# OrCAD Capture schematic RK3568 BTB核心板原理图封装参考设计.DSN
size A3; title: 野火_EBF RK3568 底板; rev: V1.0; note: BTB连接器; note: https://yehuosm.tmall.com
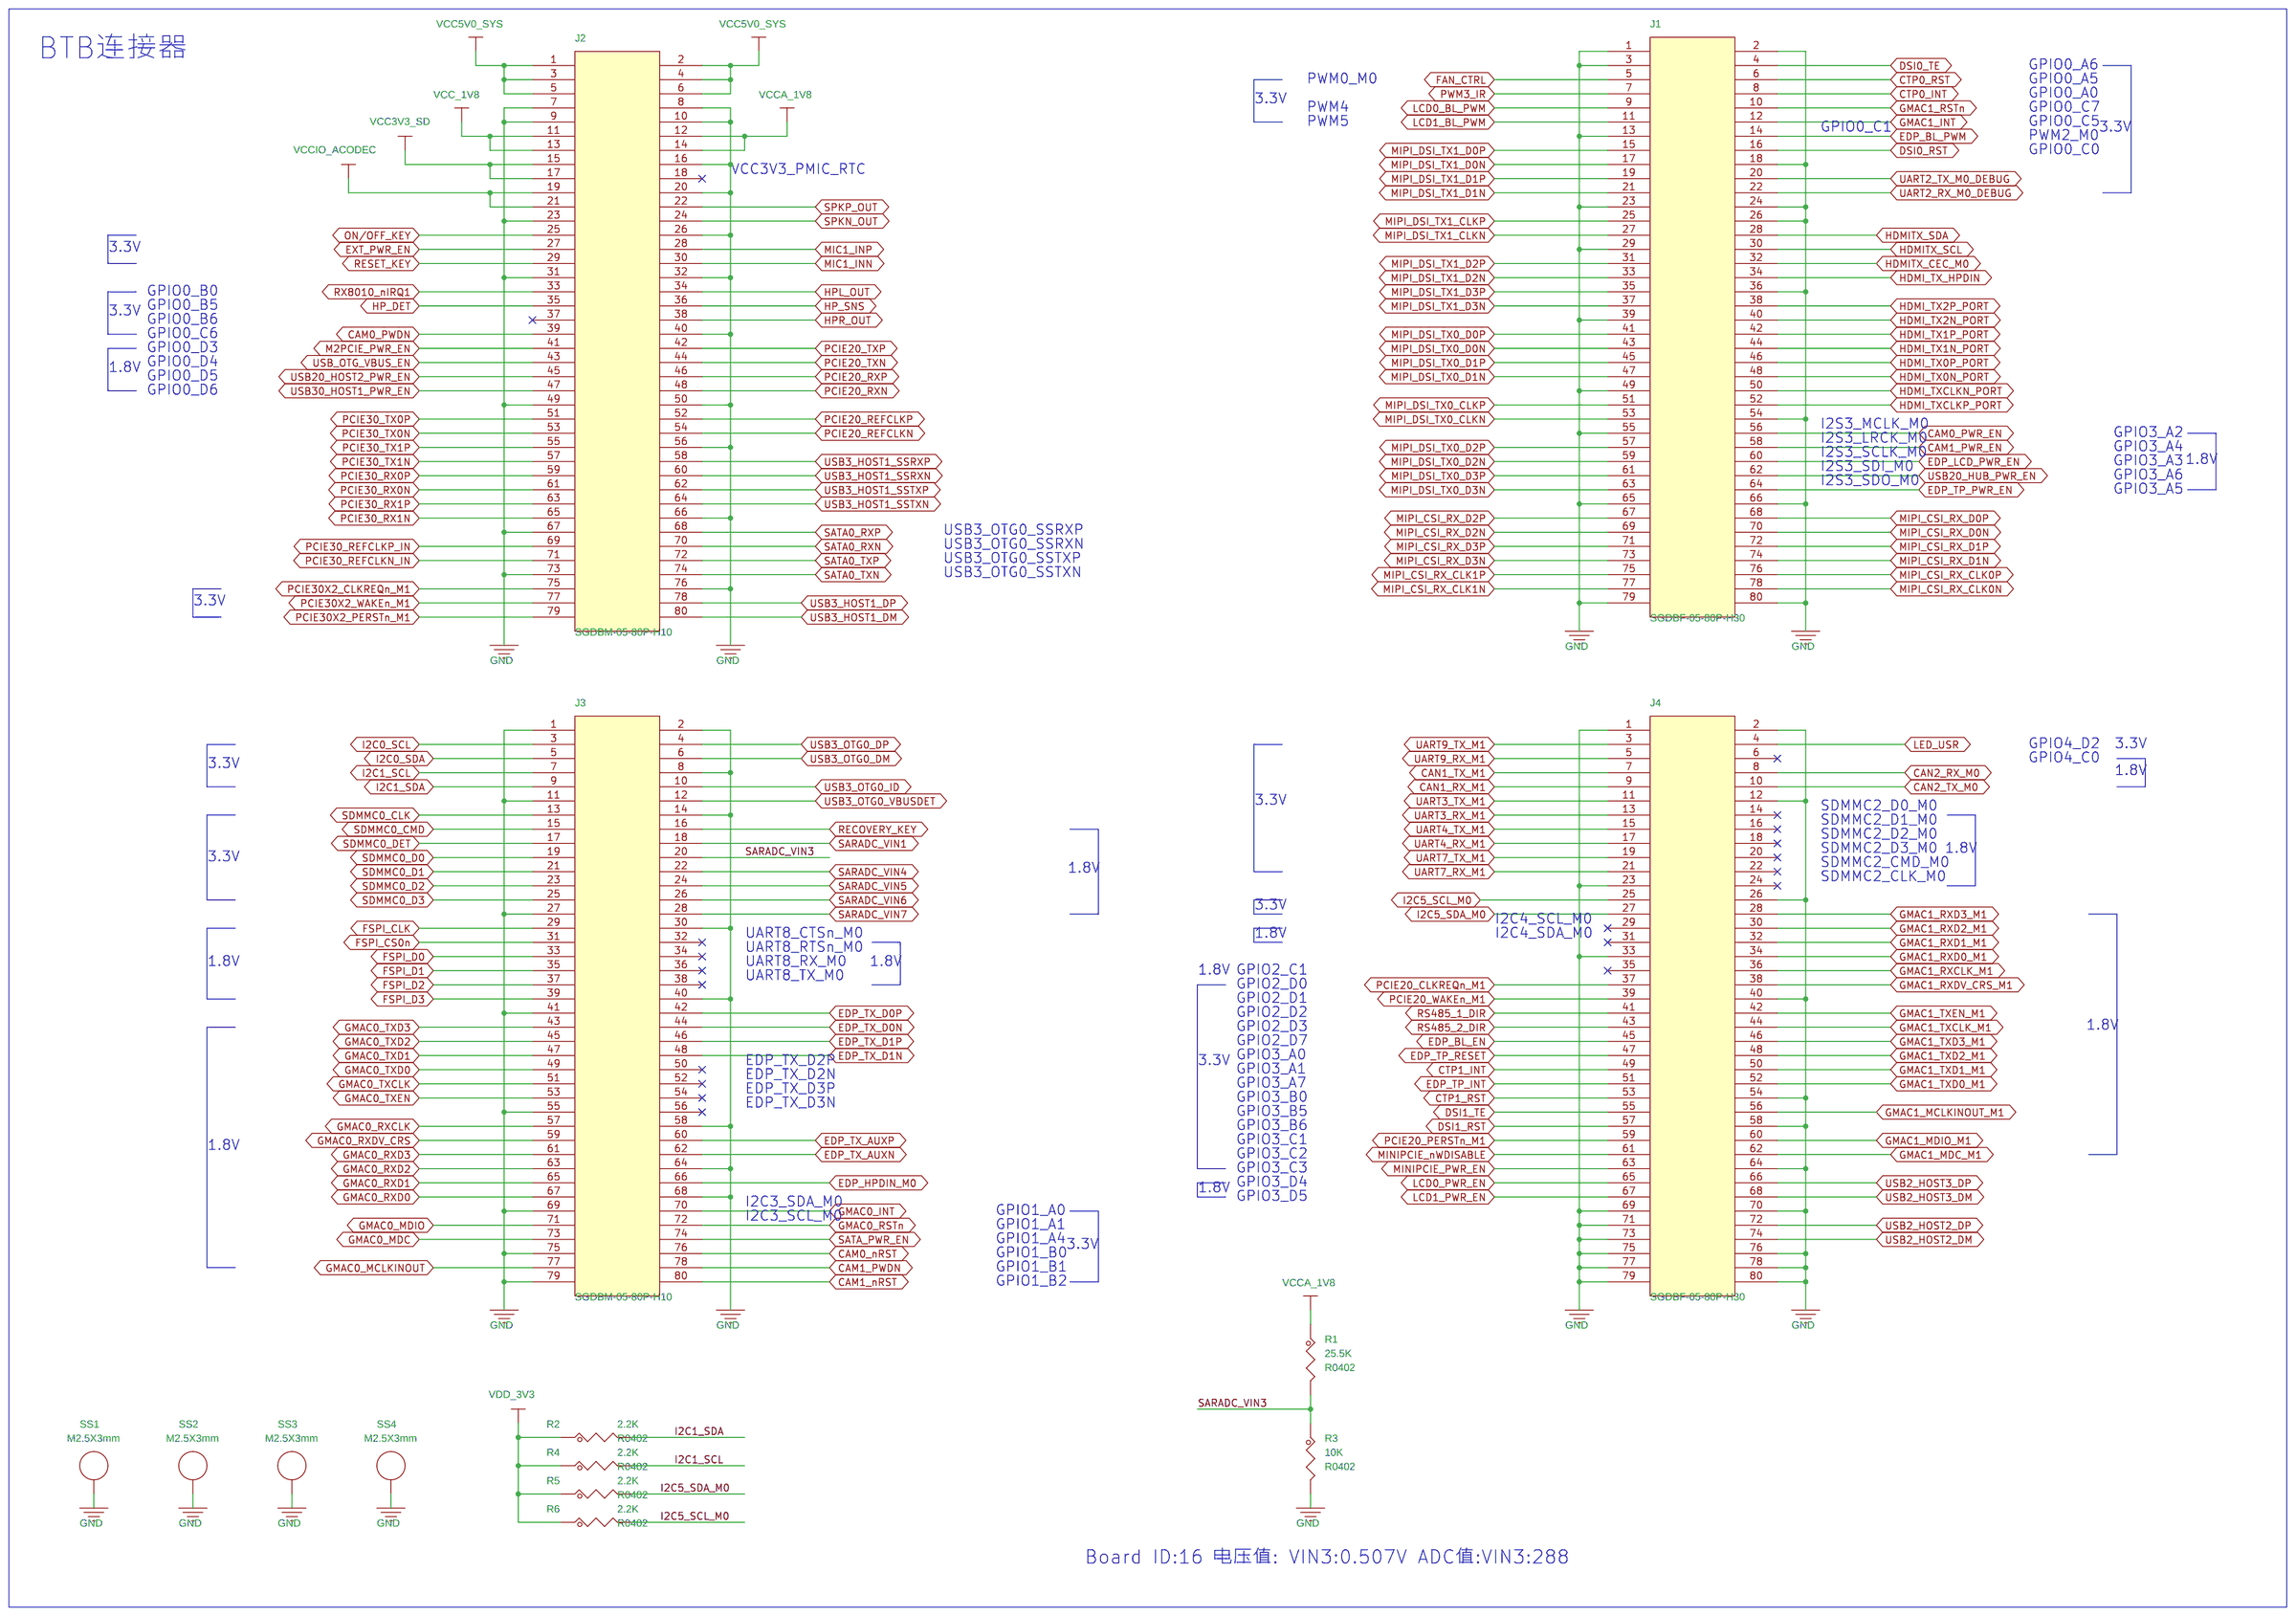
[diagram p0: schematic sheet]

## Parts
J1  SGDBF-05-80P-H30  [SGDBF-05-80P-H30]
J2  SGDBM-05-80P-H10  [SGDBM-05-80P-H10]
J3  SGDBM-05-80P-H10  [SGDBM-05-80P-H10]
J4  SGDBF-05-80P-H30  [SGDBF-05-80P-H30]
R1  25.5K  [R0402]
R2  2.2K  [R0402]
R3  10K  [R0402]
R4  2.2K  [R0402]
R5  2.2K  [R0402]
R6  2.2K  [R0402]
SS1  M2.5X3mm  [SMTSO-M2r5]
SS2  M2.5X3mm  [SMTSO-M2r5]
SS3  M2.5X3mm  [SMTSO-M2r5]
SS4  M2.5X3mm  [SMTSO-M2r5]

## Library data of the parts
J1 J4 = SGDBM-05-80P-H10: 规格: 0.5mm BTB母座2*40P 双槽 立贴式 合高4.0mm; 规格书: 山谷道_双槽板对板公母立贴式0_5mm.pdf; 类别: BTB连接器; 品牌: 山谷道; 生命周期: 量产; 条码: EBFCIS221220165510
J2 J3 = SGDBM-05-80P-H10: 规格: 0.5mm BTB公座2*40P 双槽 立贴式 合高4.0mm; 规格书: 山谷道_双槽板对板公母立贴式0_5mm.pdf; 类别: BTB连接器; 品牌: 山谷道; 生命周期: 量产; 条码: EBFCIS221220164941
R1 = RES: 规格: 贴片电阻25.5K 1% 1/16W 0402; 规格编号: CQ02WGF2552TCE; 规格书: 厚声-无铅厚膜电阻.pdf; 价格: 0.006152; 类别: 贴片电阻0402; 品牌: 厚声; 生命周期: 量产; 条码: EBF29070291
R2 R4-R6 = RES: 规格: 贴片电阻2.2K 1% 1/16W 0402; 规格编号: RI0402L2201FT; 规格书: 合科泰-RI系列电阻.pdf; 类别: 贴片电阻0402; 品牌: 合科泰; 生命周期: 量产; 条码: EBF29070051
R3 = RES: 规格: 贴片电阻10K 1% 1/16W 0402; 规格编号: 0402WGF1002TCE; 规格书: 厚声-无铅厚膜电阻.pdf; 价格: 0.002773; 类别: 贴片电阻0402; 品牌: 厚声; 生命周期: 量产; 条码: EBF29070046
SS1-SS4 = SPACER: 规格: SMT贴片螺母M2.5 台阶高度1.4MM 台阶外径：4.09MM 螺柱长度：3MM; 规格编号: SMTSO2530CTJ; 规格书: 雄和远景_SMTSO2530CTJ.pdf; 类别: 贴片螺母; 品牌: 雄和远景; 生命周期: 量产; 条码: EBFCIS221028102827

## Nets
GND: J1.1 J1.2 J1.3 J1.13 J1.18 J1.23 J1.24 J1.26 J1.29 J1.36 J1.39 J1.49 J1.54 J1.55 J1.65 J1.66 J1.79 J1.80 J2.7 J2.8 J2.9 J2.10 J2.16 J2.20 J2.23 J2.26 J2.31 J2.32 J2.40 J2.49 J2.50 J2.56 J2.66 J2.67 J2.73 J2.76 J3.1 J3.2 J3.8 J3.11 J3.14 J3.27 J3.30 J3.40 J3.41 J3.55 J3.58 J3.64 J3.68 J3.69 J3.75 J3.79 J4.1 J4.2 J4.12 J4.23 J4.26 J4.33 J4.40 J4.54 J4.58 J4.64 J4.69 J4.70 J4.71 J4.73 J4.75 J4.76 J4.77 J4.78 J4.79 J4.80 R3.2 SS1.1(NC) SS2.1(NC) SS3.1(NC) SS4.1(NC)
VCC3V3_SD: J2.15 J2.17
VCC5V0_SYS: J2.1 J2.2 J2.3 J2.4 J2.5 J2.6
VCC_1V8: J2.11 J2.13
VCCA_1V8: J2.12 J2.14 R1.1
VCCIO_ACODEC: J2.19 J2.21
VDD_3V3: R2.1 R4.1 R5.1 R6.1
CAM0_nRST: J3.76
CAM0_PWDN: J2.39
CAM0_PWR_EN: J1.56
CAM1_nRST: J3.80
CAM1_PWDN: J3.78
CAM1_PWR_EN: J1.58
CAN1_RX_M1: J4.9
CAN1_TX_M1: J4.7
CAN2_RX_M0: J4.8
CAN2_TX_M0: J4.10
CTP0_INT: J1.8
CTP0_RST: J1.6
CTP1_INT: J4.49
CTP1_RST: J4.53
DSI0_RST: J1.16
DSI0_TE: J1.4
DSI1_RST: J4.57
DSI1_TE: J4.55
EDP_BL_EN: J4.45
EDP_BL_PWM: J1.14
EDP_HPDIN_M0: J3.66
EDP_LCD_PWR_EN: J1.60
EDP_TP_INT: J4.51
EDP_TP_PWR_EN: J1.64
EDP_TP_RESET: J4.47
EDP_TX_AUXN: J3.62
EDP_TX_AUXP: J3.60
EDP_TX_D0N: J3.44
EDP_TX_D0P: J3.42
EDP_TX_D1N: J3.48
EDP_TX_D1P: J3.46
EXT_PWR_EN: J2.27
FAN_CTRL: J1.5
FSPI_CLK: J3.29
FSPI_CS0n: J3.31
FSPI_D0: J3.33
FSPI_D1: J3.35
FSPI_D2: J3.37
FSPI_D3: J3.39
GMAC0_INT: J3.70
GMAC0_MCLKINOUT: J3.77
GMAC0_MDC: J3.73
GMAC0_MDIO: J3.71
GMAC0_RSTn: J3.72
GMAC0_RXCLK: J3.57
GMAC0_RXD0: J3.67
GMAC0_RXD1: J3.65
GMAC0_RXD2: J3.63
GMAC0_RXD3: J3.61
GMAC0_RXDV_CRS: J3.59
GMAC0_TXCLK: J3.51
GMAC0_TXD0: J3.49
GMAC0_TXD1: J3.47
GMAC0_TXD2: J3.45
GMAC0_TXD3: J3.43
GMAC0_TXEN: J3.53
GMAC1_INT: J1.12
GMAC1_MCLKINOUT_M1: J4.56
GMAC1_MDC_M1: J4.62
GMAC1_MDIO_M1: J4.60
GMAC1_RSTn: J1.10
GMAC1_RXCLK_M1: J4.36
GMAC1_RXD0_M1: J4.34
GMAC1_RXD1_M1: J4.32
GMAC1_RXD2_M1: J4.30
GMAC1_RXD3_M1: J4.28
GMAC1_RXDV_CRS_M1: J4.38
GMAC1_TXCLK_M1: J4.44
GMAC1_TXD0_M1: J4.52
GMAC1_TXD1_M1: J4.50
GMAC1_TXD2_M1: J4.48
GMAC1_TXD3_M1: J4.46
GMAC1_TXEN_M1: J4.42
HDMI_TX0N_PORT: J1.48
HDMI_TX0P_PORT: J1.46
HDMI_TX1N_PORT: J1.44
HDMI_TX1P_PORT: J1.42
HDMI_TX2N_PORT: J1.40
HDMI_TX2P_PORT: J1.38
HDMI_TX_HPDIN: J1.34
HDMI_TXCLKN_PORT: J1.50
HDMI_TXCLKP_PORT: J1.52
HDMITX_CEC_M0: J1.32
HDMITX_SCL: J1.30
HDMITX_SDA: J1.28
HP_DET: J2.35
HP_SNS: J2.36
HPL_OUT: J2.34
HPR_OUT: J2.38
I2C0_SCL: J3.3
I2C0_SDA: J3.5
I2C1_SCL: J3.7 R4.2
I2C1_SDA: J3.9 R2.2
I2C5_SCL_M0: J4.25 R6.2
I2C5_SDA_M0: J4.27 R5.2
LCD0_BL_PWM: J1.9
LCD0_PWR_EN: J4.65
LCD1_BL_PWM: J1.11
LCD1_PWR_EN: J4.67
LED_USR: J4.4
M2PCIE_PWR_EN: J2.41
MIC1_INN: J2.30
MIC1_INP: J2.28
MINIPCIE_nWDISABLE: J4.61
MINIPCIE_PWR_EN: J4.63
MIPI_CSI_RX_CLK0N: J1.78
MIPI_CSI_RX_CLK0P: J1.76
MIPI_CSI_RX_CLK1N: J1.77
MIPI_CSI_RX_CLK1P: J1.75
MIPI_CSI_RX_D0N: J1.70
MIPI_CSI_RX_D0P: J1.68
MIPI_CSI_RX_D1N: J1.74
MIPI_CSI_RX_D1P: J1.72
MIPI_CSI_RX_D2N: J1.69
MIPI_CSI_RX_D2P: J1.67
MIPI_CSI_RX_D3N: J1.73
MIPI_CSI_RX_D3P: J1.71
MIPI_DSI_TX0_CLKN: J1.53
MIPI_DSI_TX0_CLKP: J1.51
MIPI_DSI_TX0_D0N: J1.43
MIPI_DSI_TX0_D0P: J1.41
MIPI_DSI_TX0_D1N: J1.47
MIPI_DSI_TX0_D1P: J1.45
MIPI_DSI_TX0_D2N: J1.59
MIPI_DSI_TX0_D2P: J1.57
MIPI_DSI_TX0_D3N: J1.63
MIPI_DSI_TX0_D3P: J1.61
MIPI_DSI_TX1_CLKN: J1.27
MIPI_DSI_TX1_CLKP: J1.25
MIPI_DSI_TX1_D0N: J1.17
MIPI_DSI_TX1_D0P: J1.15
MIPI_DSI_TX1_D1N: J1.21
MIPI_DSI_TX1_D1P: J1.19
MIPI_DSI_TX1_D2N: J1.33
MIPI_DSI_TX1_D2P: J1.31
MIPI_DSI_TX1_D3N: J1.37
MIPI_DSI_TX1_D3P: J1.35
ON/OFF_KEY: J2.25
PCIE20_CLKREQn_M1: J4.37
PCIE20_PERSTn_M1: J4.59
PCIE20_REFCLKN: J2.54
PCIE20_REFCLKP: J2.52
PCIE20_RXN: J2.48
PCIE20_RXP: J2.46
PCIE20_TXN: J2.44
PCIE20_TXP: J2.42
PCIE20_WAKEn_M1: J4.39
PCIE30_REFCLKN_IN: J2.71
PCIE30_REFCLKP_IN: J2.69
PCIE30_RX0N: J2.61
PCIE30_RX0P: J2.59
PCIE30_RX1N: J2.65
PCIE30_RX1P: J2.63
PCIE30_TX0N: J2.53
PCIE30_TX0P: J2.51
PCIE30_TX1N: J2.57
PCIE30_TX1P: J2.55
PCIE30X2_CLKREQn_M1: J2.75
PCIE30X2_PERSTn_M1: J2.79
PCIE30X2_WAKEn_M1: J2.77
PWM3_IR: J1.7
RECOVERY_KEY: J3.16
RESET_KEY: J2.29
RS485_1_DIR: J4.41
RS485_2_DIR: J4.43
RX8010_nIRQ1: J2.33
SARADC_VIN1: J3.18
SARADC_VIN3: J3.20 R1.2 R3.1
SARADC_VIN4: J3.22
SARADC_VIN5: J3.24
SARADC_VIN6: J3.26
SARADC_VIN7: J3.28
SATA0_RXN: J2.70
SATA0_RXP: J2.68
SATA0_TXN: J2.74
SATA0_TXP: J2.72
SATA_PWR_EN: J3.74
SDMMC0_CLK: J3.13
SDMMC0_CMD: J3.15
SDMMC0_D0: J3.19
SDMMC0_D1: J3.21
SDMMC0_D2: J3.23
SDMMC0_D3: J3.25
SDMMC0_DET: J3.17
SPKN_OUT: J2.24
SPKP_OUT: J2.22
UART2_RX_M0_DEBUG: J1.22
UART2_TX_M0_DEBUG: J1.20
UART3_RX_M1: J4.13
UART3_TX_M1: J4.11
UART4_RX_M1: J4.17
UART4_TX_M1: J4.15
UART7_RX_M1: J4.21
UART7_TX_M1: J4.19
UART9_RX_M1: J4.5
UART9_TX_M1: J4.3
USB2_HOST2_DM: J4.74
USB2_HOST2_DP: J4.72
USB2_HOST3_DM: J4.68
USB2_HOST3_DP: J4.66
USB3_HOST1_DM: J2.80
USB3_HOST1_DP: J2.78
USB3_HOST1_SSRXN: J2.60
USB3_HOST1_SSRXP: J2.58
USB3_HOST1_SSTXN: J2.64
USB3_HOST1_SSTXP: J2.62
USB3_OTG0_DM: J3.6
USB3_OTG0_DP: J3.4
USB3_OTG0_ID: J3.10
USB3_OTG0_VBUSDET: J3.12
USB20_HOST2_PWR_EN: J2.45
USB20_HUB_PWR_EN: J1.62
USB30_HOST1_PWR_EN: J2.47
USB_OTG_VBUS_EN: J2.43

Not connected (* = marked no-connect by the designer): J2 18* 37*; J3 32* 34* 36* 38* 50* 52* 54* 56*; J4 6* 14* 16* 18* 20* 22* 24* 29* 31* 35*

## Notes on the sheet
- BTB连接器
- GPIO0_A6
- PWM0_M0
- GPIO0_A5
- 3.3V
- GPIO0_A0
- PWM4
- GPIO0_C7
- PWM5
- GPIO0_C1
- GPIO0_C5
- PWM2_M0
- 3.3V
- GPIO0_C0
- VCC3V3_PMIC_RTC
- 3.3V
- GPIO0_B0
- 3.3V
- GPIO0_B5
- GPIO0_B6
- GPIO0_C6
- GPIO0_D3
- 1.8V
- GPIO0_D4
- GPIO0_D5
- GPIO0_D6
- I2S3_LRCK_M0
- I2S3_MCLK_M0
- GPIO3_A2
- I2S3_SCLK_M0
- GPIO3_A4
- I2S3_SDI_M0
- GPIO3_A3
- 1.8V
- I2S3_SDO_M0
- GPIO3_A6
- GPIO3_A5
- USB3_OTG0_SSRXP
- USB3_OTG0_SSRXN
- USB3_OTG0_SSTXP
- USB3_OTG0_SSTXN
- 3.3V
- GPIO4_D2
- 3.3V
- 3.3V
- GPIO4_C0
- 1.8V
- 3.3V
- SDMMC2_D0_M0
- SDMMC2_D1_M0
- SDMMC2_D2_M0
- SDMMC2_D3_M0
- 1.8V
- 3.3V
- 1.8V
- SDMMC2_CMD_M0
- SDMMC2_CLK_M0
- 3.3V
- I2C4_SCL_M0
- UART8_CTSn_M0
- 1.8V
- I2C4_SDA_M0
- UART8_RTSn_M0
- 1.8V
- UART8_RX_M0
- 1.8V
- 1.8V
- GPIO2_C1
- UART8_TX_M0
- GPIO2_D0
- GPIO2_D1
- GPIO2_D2
- GPIO2_D3
- 1.8V
- GPIO2_D7
- GPIO3_A0
- EDP_TX_D2P
- 3.3V
- GPIO3_A1
- EDP_TX_D2N
- EDP_TX_D3P
- GPIO3_A7
- EDP_TX_D3N
- GPIO3_B0
- GPIO3_B5
- GPIO3_B6
- GPIO3_C1
- 1.8V
- GPIO3_C2
- GPIO3_C3
- 1.8V
- GPIO3_D4
- I2C3_SDA_M0
- GPIO3_D5
- I2C3_SCL_M0
- GPIO1_A0
- GPIO1_A1
- GPIO1_A4
- GPIO1_B0
- 3.3V
- GPIO1_B1
- GPIO1_B2
- Board ID:16 电压值: VIN3:0.507V ADC值:VIN3:288
